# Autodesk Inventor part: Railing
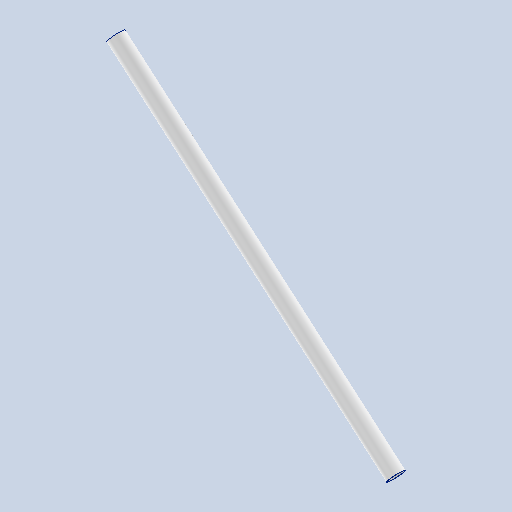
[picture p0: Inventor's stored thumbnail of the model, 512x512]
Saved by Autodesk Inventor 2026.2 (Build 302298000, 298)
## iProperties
Created: 2022-06
Part Number: Railing
Material: Aluminum 6061
Document SubType Name: Modeling
Designer: reaumed
Density: 2.7 g/cm^3
Appearance: Aluminum - Flat
Mass: 1627.16 g
Surface Area: 4753.01 cm^2
Volume: 602.654 cm^3
Author: reaumed
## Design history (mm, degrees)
workplane "Work Plane1"
workplane "Work Plane3"
  workplane "Work Plane2"
workplane "Work Plane4"
revolve "Revolution1" stored, may be unused: angle "d19" = 360 deg
shell "Shell1" dims "d20" = 2.54
body "Solid2"
sketch "Sketch1"
  geometry: L1 (0, 819.15)-(-914.4, 57.15); L2 (-1677.378, 723.9)-(342.267, 723.9) reference; L3 (-1677.378, -190.5)-(342.267, -190.5) reference; L4 (-16.261, 838.663)-(-930.661, 76.663); L5 (-114.3, -730.16)-(-114.3, 1150.93) reference; L6 (0, -730.16)-(0, 1150.93) reference; L7 (0, 819.15)-(-16.261, 838.663); L8 (-914.4, 57.15)-(-930.661, 76.663); L9 (50.643, 758.378)-(-922.53, 66.906); 5 further points
  constraints: 10 end point, 6 point on line, 2 perpendicular, 1 midpoint, 1 parallel
  dimensions: "d4" = 39.8056 deg angle of L1 L3 (= RailingAngle); "d12" = 25.4 distance between parallel lines of L1 L4 (= 0.5 x RailingThickness); "d13" = 0 distance from line of L2 point (-114.3, 723.9); "d14" = 914.4 distance from line of point (-914.4, -61.819) L6 (= RailingRun); "d16" = 1190.28205 distance of L1.start L1.end (= RailingStockLength)
other parameters: "Width" = 762 [user parameter; used in 1 equation term], "Rise" = 190.5 [user parameter; used in 1 equation term], "Run" = 228.6 [user parameter; used in 1 equation term], "RailingWidth" = 76.2 [user parameter], "RailingThickness" = 50.8 [user parameter; used in 2 equation terms], "RailingStockLength" = 1190.28205 [user parameter; used in 1 equation term], "RailingAngle" = 39.8056 deg [user parameter; used in 1 equation term], "d0" = 361.95 (= 0.5 x Width - 0.5 x StringerThickness), "BalusterLength" = 914.4 [user parameter; used in 1 equation term], "d1" = -190.5 (= -Rise), "d2" = 914.4 (= BalusterLength), "d6" = 50.8 (= RailingThickness), "d11" = 114.3 (= 0.5 x Run), "RailingRun" = 914.4 [user parameter; used in 1 equation term], "d15" = 1808.46777 (derived), "StringerThickness" = 38.1 [user parameter; used in 1 equation term]
